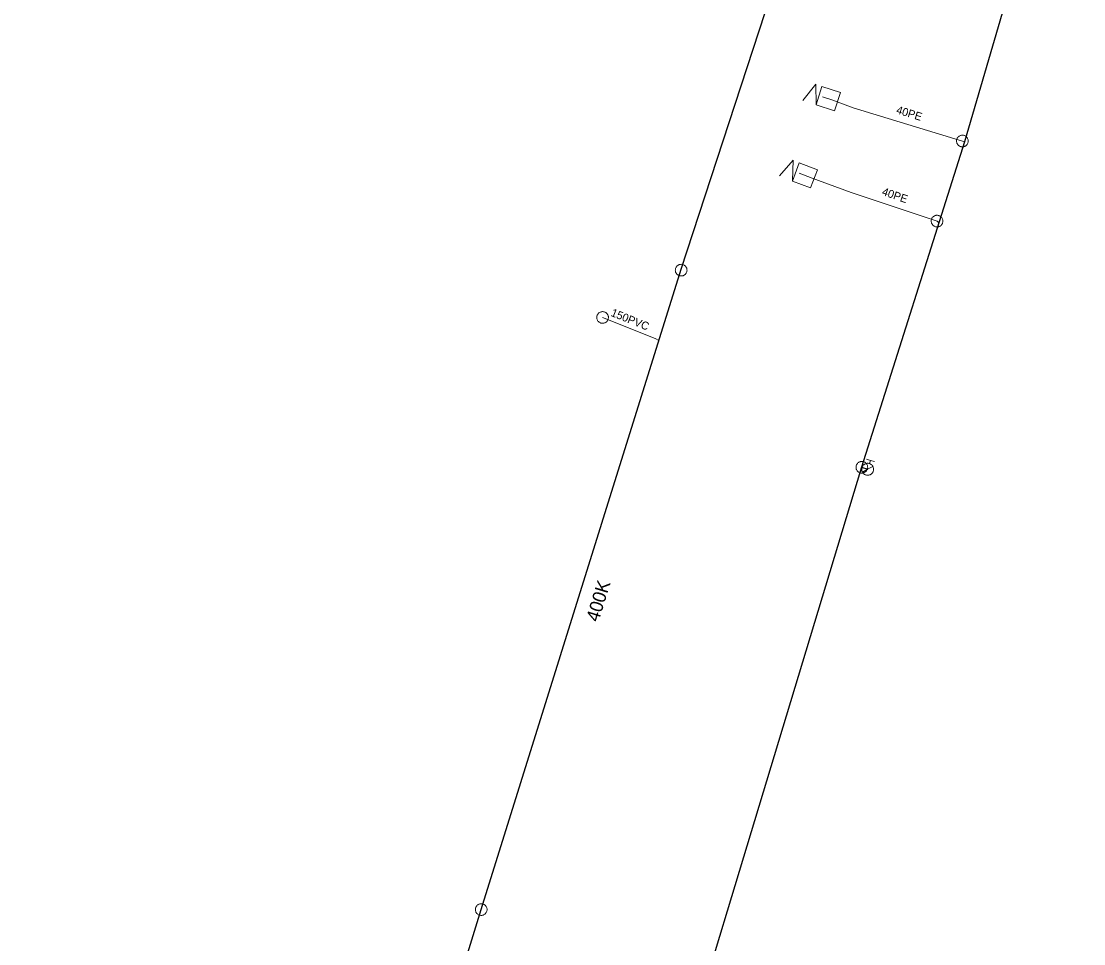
# Model space of a CAD drawing. Extents: x -741806 to -738704, y -1059275 to -1055387.
# Drawn here: x -740396.2 to -740316.6, y -1057053.7 to -1056984.6 of the extents above; entities that cross this region are included whole.
import ezdxf

# ---------------------------------------------------------------- set-up
doc = ezdxf.new("R2010")
doc.units = 0
doc.header["$LTSCALE"] = 0.4
for name, color, linetype, lineweight in [('2', 7, 'Continuous', 25), ('21', 7, 'Continuous', 13), ('3', 7, 'Continuous', 13), ('46', 7, 'Continuous', 13), ('50', 7, 'Continuous', 13), ('51', 7, 'Continuous', 13), ('52', 7, 'Continuous', 25), ('56', 7, 'Continuous', 13), ('60', 7, 'Continuous', 13)]:
    doc.layers.add(name, color=color, linetype=linetype, lineweight=lineweight)
for name, color, linetype in [('5', 7, 'Continuous'), ('54', 7, 'Continuous'), ('55', 7, 'Continuous')]:
    doc.layers.add(name, color=color, linetype=linetype)

msp = doc.modelspace()

# ---------------------------------------------------------------- linework, layer by layer
at = {"layer": '2'}
msp.add_lwpolyline([(-740396.239, -1057164.08), (-740391.449, -1057147.19), (-740376.449, -1057098.879), (-740361.75, -1057051.12), (-740346.756, -1057003.12), (-740332.78, -1056960.44)], dxfattribs=at)
at = {"layer": '21'}
for points in [[(-740325.5, -1056993.58), (-740325.67, -1056993.53), (-740333.87, -1056991.05), (-740335.469, -1056990.429), (-740336.157, -1056990.21)], [(-740327.424, -1056999.655), (-740327.57, -1056999.53), (-740333.998, -1056997.373), (-740336.924, -1056996.305), (-740337.899, -1056995.94)]]:
    msp.add_lwpolyline(points, dxfattribs=at)
at = {"layer": '3'}
for points in [[(-740346.625, -1057002.786), (-740346.669, -1057002.775), (-740346.714, -1057002.768), (-740346.761, -1057002.766), (-740346.806, -1057002.769), (-740346.851, -1057002.777), (-740346.896, -1057002.789), (-740346.938, -1057002.806), (-740346.979, -1057002.827), (-740347.016, -1057002.853), (-740347.052, -1057002.882), (-740347.084, -1057002.915), (-740347.113, -1057002.951), (-740347.136, -1057002.989), (-740347.158, -1057003.03), (-740347.173, -1057003.073), (-740347.185, -1057003.118), (-740347.191, -1057003.163), (-740347.193, -1057003.208), (-740347.19, -1057003.255), (-740347.182, -1057003.3), (-740347.17, -1057003.344), (-740347.153, -1057003.385), (-740347.132, -1057003.427), (-740347.107, -1057003.465), (-740347.077, -1057003.5), (-740347.044, -1057003.532), (-740347.009, -1057003.56), (-740346.97, -1057003.585), (-740346.929, -1057003.605), (-740346.885, -1057003.621), (-740346.842, -1057003.633), (-740346.797, -1057003.639), (-740346.75, -1057003.641), (-740346.704, -1057003.638), (-740346.66, -1057003.631), (-740346.615, -1057003.618), (-740346.573, -1057003.601), (-740346.532, -1057003.58), (-740346.495, -1057003.555), (-740346.46, -1057003.526), (-740346.427, -1057003.493), (-740346.398, -1057003.457), (-740346.374, -1057003.418), (-740346.354, -1057003.378), (-740346.338, -1057003.334), (-740346.326, -1057003.29), (-740346.319, -1057003.245), (-740346.318, -1057003.199), (-740346.321, -1057003.153), (-740346.329, -1057003.108), (-740346.341, -1057003.064), (-740346.357, -1057003.021), (-740346.379, -1057002.981), (-740346.404, -1057002.943), (-740346.434, -1057002.907), (-740346.467, -1057002.875), (-740346.502, -1057002.847), (-740346.542, -1057002.822), (-740346.582, -1057002.802), (-740346.624, -1057002.786)], [(-740361.62, -1057050.701), (-740361.664, -1057050.691), (-740361.709, -1057050.684), (-740361.756, -1057050.682), (-740361.801, -1057050.685), (-740361.846, -1057050.693), (-740361.891, -1057050.706), (-740361.932, -1057050.723), (-740361.973, -1057050.744), (-740362.011, -1057050.77), (-740362.046, -1057050.799), (-740362.078, -1057050.832), (-740362.107, -1057050.868), (-740362.13, -1057050.907), (-740362.151, -1057050.948), (-740362.167, -1057050.991), (-740362.178, -1057051.036), (-740362.184, -1057051.081), (-740362.186, -1057051.126), (-740362.183, -1057051.172), (-740362.175, -1057051.218), (-740362.162, -1057051.261), (-740362.146, -1057051.303), (-740362.124, -1057051.344), (-740362.099, -1057051.382), (-740362.069, -1057051.418), (-740362.036, -1057051.449), (-740362, -1057051.478), (-740361.961, -1057051.502), (-740361.92, -1057051.522), (-740361.877, -1057051.538), (-740361.833, -1057051.549), (-740361.788, -1057051.555), (-740361.741, -1057051.557), (-740361.695, -1057051.554), (-740361.651, -1057051.546), (-740361.607, -1057051.534), (-740361.565, -1057051.516), (-740361.523, -1057051.495), (-740361.486, -1057051.469), (-740361.451, -1057051.44), (-740361.419, -1057051.407), (-740361.39, -1057051.371), (-740361.366, -1057051.333), (-740361.346, -1057051.292), (-740361.33, -1057051.248), (-740361.319, -1057051.204), (-740361.312, -1057051.159), (-740361.311, -1057051.113), (-740361.314, -1057051.067), (-740361.322, -1057051.022), (-740361.335, -1057050.978), (-740361.351, -1057050.936), (-740361.373, -1057050.895), (-740361.398, -1057050.857), (-740361.428, -1057050.822), (-740361.461, -1057050.79), (-740361.497, -1057050.762), (-740361.536, -1057050.737), (-740361.577, -1057050.717), (-740361.619, -1057050.701)]]:
    msp.add_lwpolyline(points, dxfattribs=at)
at = {"layer": '46'}
msp.add_lwpolyline([(-740352.242, -1057006.912), (-740352.228, -1057006.869), (-740352.218, -1057006.825), (-740352.212, -1057006.779), (-740352.211, -1057006.734), (-740352.215, -1057006.688), (-740352.224, -1057006.642), (-740352.238, -1057006.599), (-740352.255, -1057006.556), (-740352.278, -1057006.517), (-740352.304, -1057006.48), (-740352.335, -1057006.445), (-740352.368, -1057006.413), (-740352.405, -1057006.387), (-740352.444, -1057006.362), (-740352.486, -1057006.343), (-740352.529, -1057006.328), (-740352.574, -1057006.319), (-740352.619, -1057006.313), (-740352.665, -1057006.312), (-740352.711, -1057006.317), (-740352.755, -1057006.326), (-740352.798, -1057006.339), (-740352.841, -1057006.357), (-740352.881, -1057006.379), (-740352.919, -1057006.406), (-740352.953, -1057006.436), (-740352.984, -1057006.469), (-740353.012, -1057006.506), (-740353.035, -1057006.545), (-740353.054, -1057006.587), (-740353.069, -1057006.63), (-740353.079, -1057006.674), (-740353.085, -1057006.72), (-740353.085, -1057006.767), (-740353.082, -1057006.811), (-740353.073, -1057006.857), (-740353.059, -1057006.9), (-740353.041, -1057006.943), (-740353.019, -1057006.982), (-740352.993, -1057007.019), (-740352.962, -1057007.054), (-740352.929, -1057007.086), (-740352.892, -1057007.113), (-740352.853, -1057007.137), (-740352.811, -1057007.156), (-740352.768, -1057007.171), (-740352.724, -1057007.181), (-740352.678, -1057007.186), (-740352.632, -1057007.187), (-740352.586, -1057007.182), (-740352.542, -1057007.173), (-740352.498, -1057007.161), (-740352.456, -1057007.142), (-740352.416, -1057007.12), (-740352.378, -1057007.093), (-740352.343, -1057007.063), (-740352.313, -1057007.03), (-740352.285, -1057006.993), (-740352.262, -1057006.954), (-740352.242, -1057006.913)], dxfattribs=at)
at = {"layer": '50'}
for p, q in [((-740332.852, -1057017.365), (-740332.559, -1057017.459)), ((-740332.635, -1057017.698), (-740332.559, -1057017.459)), ((-740332.266, -1057017.553), (-740332.559, -1057017.459)), ((-740332.771, -1057018.124), (-740333.17, -1057018.329)), ((-740332.771, -1057018.124), (-740332.376, -1057017.923))]:
    msp.add_line(p, q, dxfattribs=at)
msp.add_lwpolyline([(-740332.349, -1057018.263), (-740332.337, -1057018.216), (-740332.328, -1057018.17), (-740332.326, -1057018.123), (-740332.329, -1057018.076), (-740332.335, -1057018.033), (-740332.348, -1057017.985), (-740332.365, -1057017.943), (-740332.386, -1057017.9), (-740332.41, -1057017.86), (-740332.441, -1057017.825), (-740332.473, -1057017.792), (-740332.508, -1057017.761), (-740332.549, -1057017.737), (-740332.59, -1057017.715), (-740332.633, -1057017.698), (-740332.678, -1057017.687), (-740332.722, -1057017.678), (-740332.77, -1057017.677), (-740332.817, -1057017.679), (-740332.865, -1057017.686), (-740332.908, -1057017.698), (-740332.953, -1057017.715), (-740332.994, -1057017.736), (-740333.032, -1057017.761), (-740333.07, -1057017.79), (-740333.104, -1057017.823), (-740333.132, -1057017.859), (-740333.16, -1057017.898), (-740333.178, -1057017.941), (-740333.198, -1057017.982), (-740333.21, -1057018.029), (-740333.216, -1057018.075), (-740333.219, -1057018.12), (-740333.218, -1057018.168), (-740333.209, -1057018.214), (-740333.199, -1057018.26), (-740333.181, -1057018.302), (-740333.161, -1057018.345), (-740333.134, -1057018.385), (-740333.105, -1057018.42), (-740333.071, -1057018.454), (-740333.035, -1057018.482), (-740332.998, -1057018.509), (-740332.954, -1057018.531), (-740332.911, -1057018.548), (-740332.867, -1057018.559), (-740332.82, -1057018.566), (-740332.773, -1057018.569), (-740332.727, -1057018.567), (-740332.68, -1057018.559), (-740332.636, -1057018.548), (-740332.591, -1057018.531), (-740332.551, -1057018.511), (-740332.511, -1057018.486), (-740332.476, -1057018.455), (-740332.441, -1057018.424), (-740332.411, -1057018.387), (-740332.388, -1057018.347), (-740332.366, -1057018.306)], close=True, dxfattribs=at)
at = {"layer": '51'}
for points in [[(-740326.089, -1056993.406), (-740326.099, -1056993.449), (-740326.105, -1056993.495), (-740326.107, -1056993.541), (-740326.103, -1056993.586), (-740326.094, -1056993.631), (-740326.081, -1056993.676), (-740326.064, -1056993.717), (-740326.042, -1056993.758), (-740326.016, -1056993.795), (-740325.986, -1056993.83), (-740325.953, -1056993.862), (-740325.916, -1056993.89), (-740325.877, -1056993.914), (-740325.836, -1056993.933), (-740325.793, -1056993.948), (-740325.748, -1056993.959), (-740325.703, -1056993.965), (-740325.657, -1056993.966), (-740325.611, -1056993.962), (-740325.566, -1056993.953), (-740325.522, -1056993.94), (-740325.48, -1056993.923), (-740325.44, -1056993.901), (-740325.402, -1056993.875), (-740325.367, -1056993.845), (-740325.336, -1056993.812), (-740325.308, -1056993.776), (-740325.284, -1056993.736), (-740325.265, -1056993.695), (-740325.249, -1056993.652), (-740325.239, -1056993.608), (-740325.233, -1056993.562), (-740325.232, -1056993.516), (-740325.235, -1056993.471), (-740325.244, -1056993.426), (-740325.257, -1056993.381), (-740325.275, -1056993.34), (-740325.296, -1056993.299), (-740325.323, -1056993.262), (-740325.352, -1056993.227), (-740325.386, -1056993.195), (-740325.422, -1056993.167), (-740325.461, -1056993.144), (-740325.502, -1056993.124), (-740325.546, -1056993.109), (-740325.59, -1056993.098), (-740325.636, -1056993.093), (-740325.681, -1056993.091), (-740325.727, -1056993.095), (-740325.773, -1056993.104), (-740325.816, -1056993.117), (-740325.858, -1056993.134), (-740325.898, -1056993.156), (-740325.936, -1056993.182), (-740325.971, -1056993.212), (-740326.003, -1056993.245), (-740326.03, -1056993.281), (-740326.054, -1056993.321), (-740326.074, -1056993.362), (-740326.088, -1056993.405)], [(-740327.9, -1056999.244), (-740327.928, -1056999.279), (-740327.952, -1056999.318), (-740327.972, -1056999.36), (-740327.988, -1056999.402), (-740327.999, -1056999.447), (-740328.005, -1056999.492), (-740328.006, -1056999.538), (-740328.003, -1056999.584), (-740327.994, -1056999.628), (-740327.982, -1056999.672), (-740327.965, -1056999.715), (-740327.943, -1056999.756), (-740327.918, -1056999.794), (-740327.888, -1056999.828), (-740327.855, -1056999.86), (-740327.819, -1056999.889), (-740327.78, -1056999.913), (-740327.739, -1056999.932), (-740327.695, -1056999.947), (-740327.65, -1056999.958), (-740327.605, -1056999.964), (-740327.56, -1056999.967), (-740327.514, -1056999.963), (-740327.469, -1056999.955), (-740327.425, -1056999.942), (-740327.382, -1056999.924), (-740327.342, -1056999.903), (-740327.304, -1056999.877), (-740327.269, -1056999.847), (-740327.237, -1056999.815), (-740327.21, -1056999.778), (-740327.186, -1056999.74), (-740327.165, -1056999.698), (-740327.15, -1056999.656), (-740327.139, -1056999.611), (-740327.133, -1056999.565), (-740327.132, -1056999.52), (-740327.134, -1056999.474), (-740327.143, -1056999.429), (-740327.156, -1056999.385), (-740327.173, -1056999.343), (-740327.195, -1056999.302), (-740327.221, -1056999.265), (-740327.25, -1056999.229), (-740327.283, -1056999.198), (-740327.319, -1056999.169), (-740327.358, -1056999.146), (-740327.399, -1056999.125), (-740327.443, -1056999.11), (-740327.487, -1056999.099), (-740327.532, -1056999.093), (-740327.578, -1056999.091), (-740327.624, -1056999.095), (-740327.669, -1056999.103), (-740327.713, -1056999.116), (-740327.756, -1056999.133), (-740327.795, -1056999.154), (-740327.834, -1056999.181), (-740327.868, -1056999.21), (-740327.899, -1056999.243)], [(-740332.79, -1057018.106), (-740332.778, -1057018.063), (-740332.771, -1057018.018), (-740332.768, -1057017.972), (-740332.771, -1057017.927), (-740332.778, -1057017.881), (-740332.79, -1057017.836), (-740332.807, -1057017.794), (-740332.827, -1057017.753), (-740332.853, -1057017.715), (-740332.882, -1057017.68), (-740332.914, -1057017.647), (-740332.95, -1057017.618), (-740332.988, -1057017.593), (-740333.029, -1057017.573), (-740333.072, -1057017.557), (-740333.117, -1057017.545), (-740333.162, -1057017.538), (-740333.207, -1057017.536), (-740333.253, -1057017.539), (-740333.299, -1057017.546), (-740333.343, -1057017.558), (-740333.385, -1057017.574), (-740333.426, -1057017.596), (-740333.464, -1057017.62), (-740333.5, -1057017.65), (-740333.532, -1057017.682), (-740333.561, -1057017.717), (-740333.586, -1057017.757), (-740333.606, -1057017.797), (-740333.623, -1057017.84), (-740333.634, -1057017.884), (-740333.641, -1057017.929), (-740333.643, -1057017.975), (-740333.641, -1057018.02), (-740333.633, -1057018.066), (-740333.622, -1057018.11), (-740333.605, -1057018.153), (-740333.584, -1057018.194), (-740333.559, -1057018.232), (-740333.53, -1057018.267), (-740333.497, -1057018.299), (-740333.462, -1057018.329), (-740333.423, -1057018.353), (-740333.383, -1057018.374), (-740333.339, -1057018.39), (-740333.295, -1057018.402), (-740333.25, -1057018.408), (-740333.205, -1057018.411), (-740333.158, -1057018.408), (-740333.113, -1057018.401), (-740333.069, -1057018.389), (-740333.026, -1057018.373), (-740332.986, -1057018.351), (-740332.947, -1057018.327), (-740332.912, -1057018.297), (-740332.879, -1057018.265), (-740332.851, -1057018.23), (-740332.826, -1057018.19), (-740332.806, -1057018.15), (-740332.79, -1057018.107)]]:
    msp.add_lwpolyline(points, dxfattribs=at)
at = {"layer": '52'}
msp.add_line((-740333.225, -1057017.973), (-740332.77, -1057018.12), dxfattribs=at)
msp.add_lwpolyline([(-740316.568, -1056963.017), (-740325.5, -1056993.58), (-740333.225, -1057017.973), (-740378.526, -1057167.571), (-740379.354, -1057170.267)], dxfattribs=at)
at = {"layer": '56'}
msp.add_lwpolyline([(-740352.649, -1057006.75), (-740348.71, -1057008.33), (-740348.425, -1057008.463)], dxfattribs=at)
at = {"layer": '60'}
for points in [[(-740336.643, -1056990.803), (-740336.67, -1056989.26), (-740337.629, -1056990.487)], [(-740338.414, -1056996.508), (-740338.365, -1056994.967), (-740339.383, -1056996.145)]]:
    msp.add_lwpolyline(points, dxfattribs=at)
for points in [[(-740334.818, -1056989.88), (-740335.26, -1056991.263), (-740336.643, -1056990.821), (-740336.2, -1056989.438)], [(-740336.545, -1056995.676), (-740337.054, -1056997.036), (-740338.414, -1056996.526), (-740337.905, -1056995.167)]]:
    msp.add_lwpolyline(points, close=True, dxfattribs=at)

# ---------------------------------------------------------------- texts
at = {"layer": '5'}
msp.add_text('400K', height=1, rotation=73, dxfattribs=at).set_placement((-740352.954, -1057029.62))
at = {"layer": '54'}
for rotation, p in [(343, (-740330.676, -1056991.448)), (341, (-740331.749, -1056997.556))]:
    msp.add_text('40PE', height=0.6, rotation=rotation, dxfattribs=at).set_placement(p)
at = {"layer": '55'}
msp.add_text('150PVC', height=0.6, rotation=338, dxfattribs=at).set_placement((-740352.078, -1057006.617))

doc.saveas('drawing.dxf')
